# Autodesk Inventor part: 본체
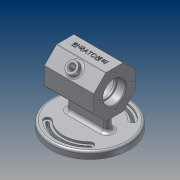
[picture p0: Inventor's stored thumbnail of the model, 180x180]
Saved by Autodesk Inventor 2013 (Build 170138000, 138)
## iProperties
Created: 2017-06
Part Number: 본체
Material: 알루미늄 6061
Document SubType Name: Modeling
Designer: Windows7
Density: 2.71 g/cm^3
Mass: 559.992 g
Surface Area: 567.6 cm^2
Volume: 206.639 cm^3
Author: Windows7
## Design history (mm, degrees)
sketch "스케치1" dims "d0" = 60
  geometry: L1 (12.426, 30)-(30, 12.426); L2 (30, 12.426)-(30, -12.426); L3 (30, -12.426)-(12.426, -30); L4 (12.426, -30)-(-12.426, -30); L5 (-12.426, -30)-(-30, -12.426); L6 (-30, -12.426)-(-30, 12.426); L7 (-30, 12.426)-(-12.426, 30); L8 (-12.426, 30)-(12.426, 30); 4 further points
  constraints: 16 end point, 2 coincident, 2 vertical alignment, 1 midpoint, 19 other
extrude "돌출1" new body sketch "스케치1" stored distance "d1" = 70; taper "d2" = 0 deg
sketch "스케치2"
  geometry: C1 r 25 at (0, 0); 1 further point
  constraints: 1 centre point, 1 coincident
  dimensions: "d3" = 50 diameter of C1
extrude "돌출2" cut sketch "스케치2" stored distance "d4" = 40; taper "d5" = 0 deg
sketch "스케치3"
  geometry: 1 further point
hole "구멍1" sketch "스케치3" at (0, 0) diameter "d6" = 28; stored, may be unused: countersink angle "d10" = 90 deg, drill point angle "d12" = 0 deg; dims "d7" = 6, "d8" = 32, "d9" = 12, "d11" = 15
chamfer "모따기1" distance "d13" = 1; stored, may be unused: second distance "d14" = 2, angle "d15" = 45 deg
node "작업 평면1"
sketch "스케치4"
  geometry: C1 r 55 at (0, 0); 1 further point
  constraints: 1 centre point, 1 coincident
  dimensions: "d17" = 110 diameter of C1
extrude "돌출3" join sketch "스케치4" distance "d18" = 10; taper "d19" = 0 deg
sketch "스케치5" dims "d20" = 86
  geometry: L1 (0, 55)-(0, -55); L2 (0, 0)-(-38.891, 38.891); A1 r 55 centre (0, 0) between (0, 55) and (0, -55) reference; A2 r 48 centre (0, 0) between (33.941, 33.941) and (-33.941, 33.941); A3 r 38 centre (0, 0) between (26.87, 26.87) and (-26.87, 26.87); A4 r 5 centre (-30.406, 30.406) between (-33.941, 33.941) and (-26.87, 26.87); A5 r 5 centre (30.406, 30.406) between (26.87, 26.87) and (33.941, 33.941)
  constraints: 11 point on circle, 4 centre point, 4 end point, 2 coincident, 1 midpoint, 1 point on line, 1 symmetric about line, 1 tangent, 1 vertical, 4 other
  dimensions: "d21" = 45 deg angle of L1 L2; "d23" = 96 diameter of A2; "d24" = 76 diameter of A3
extrude "돌출4" cut sketch "스케치5" distance "d25" = 3; taper "d26" = 0 deg
sketch "스케치6"
  geometry: A1 r 5 centre (-30.406, 30.406) between (-33.941, 33.941) and (-26.87, 26.87) reference; A2 r 38 centre (0, 0) between (26.87, 26.87) and (-26.87, 26.87) reference; A3 r 5 centre (30.406, 30.406) between (26.87, 26.87) and (33.941, 33.941) reference; A4 r 48 centre (0, 0) between (33.941, 33.941) and (-33.941, 33.941) reference; A5 r 2 centre (-30.406, 30.406) between (-31.82, 31.82) and (-28.991, 28.991); A6 r 41 centre (0, 0) between (28.991, 28.991) and (-28.991, 28.991); A7 r 2 centre (30.406, 30.406) between (28.991, 28.991) and (31.82, 31.82); A8 r 45 centre (0, 0) between (31.82, 31.82) and (-31.82, 31.82)
  constraints: 8 point on circle, 4 centre point, 3 other
  dimensions: "d27" = 3 radial gap between concentric circles of A8 A4
extrude "돌출5" cut sketch "스케치6" stored distance "d28" = 3; taper "d29" = 0 deg
sketch "스케치8"
  geometry: L1 (-24, -5)-(24, -5); L2 (24, -5)-(24, 5); L3 (24, 5)-(-24, 5); L4 (-24, 5)-(-24, -5); L5 (-24, -5)-(24, 5); L6 (24, -5)-(-24, 5); A1 r 38 centre (0, 0) between (-26.87, -26.87) and (26.87, -26.87) reference; 4 further points
  constraints: 12 end point, 5 midpoint, 2 parallel, 2 vertical alignment, 1 coincident, 1 horizontal, 1 perpendicular, 4 other
  dimensions: "d30" = 48 distance of L2.end L3.end; "d32" = 10 distance of L1.end L2.end
extrude "돌출6" join sketch "스케치8" stored distance "d33" = 3; taper "d34" = 0 deg
sketch "스케치9"
  geometry: L1 (70, 42.426)-(0, 42.426) reference; L2 (0, 24.853)-(0, 42.426) reference; 2 further points
  constraints: 1 other
  dimensions: "d36" = 30 distance from line of L1 point (35, 12.426); "d73" = 35 distance from line of point (35, 12.426) L2
feature "엠보싱1" sketch "스케치9" dims "d37" = 0.5, "d38" = 0
sketch "스케치10"
  geometry: L1 (30, 12.426)-(12.426, 30) reference; L2 (12.426, 30)-(-12.426, 30) reference; L3 (-12.426, 30)-(-30, 12.426) reference; L4 (-30, 12.426)-(-30, -12.426) reference; L5 (-30, -12.426)-(-12.426, -30) reference; L6 (-12.426, -30)-(12.426, -30) reference; L7 (12.426, -30)-(30, -12.426) reference; L8 (30, -12.426)-(30, 12.426) reference; L9 (30, 0)-(-30, 0); L10 (0, 0)-(26.163, 26.163); C1 r 17 at (0, 0) reference; 1 further point
  constraints: 5 end point, 3 midpoint
  dimensions: "d42" = 45 deg angle of L10 L9; "d43" = 7 distance from line of L10.end L1
  node "투영된 루프1"
node "작업 평면2"
sketch "스케치11"
  geometry: C1 r 8 at (0, 0); 1 further point
  constraints: 1 centre point, 1 coincident
  dimensions: "d44" = 16 diameter of C1
extrude "돌출7" join sketch "스케치11" stored distance "d45" = 3; taper "d46" = 0 deg
sketch "스케치12"
  geometry: C1 r 8 at (0, 0) reference
hole "구멍2" sketch "스케치12" at (0, 0) diameter "d47" = 8; stored, may be unused: countersink angle "d51" = 90 deg, drill point angle "d53" = 0 deg; dims "d48" = 6, "d49" = 32, "d50" = 12, "d52" = 15
fillet "모깎기1" dims "d54" = 3
chamfer "모따기2" distance "d55" = 1; stored, may be unused: second distance "d56" = 2, angle "d57" = 45 deg
fillet "모깎기2" dims "d58" = 1
fillet "모깎기3" dims "d59" = 0.3
fillet "모깎기4" dims "d60" = 3
sketch "스케치13"
  geometry: C1 r 17 at (0, 0) reference; 1 further point
  constraints: 1 vertical alignment
  dimensions: "d62" = 23 distance of C1.centre point (0, 23)
hole "구멍3" sketch "스케치13" at (0, 23) diameter "d63" = 3.242; stored, may be unused: countersink angle "d67" = 90 deg, drill point angle "d69" = 118 deg; dims "d64" = 8, "d65" = 32, "d66" = 12, "d68" = 10
fillet "모깎기6" dims "d74" = 5
fillet "모깎기7" dims "d75" = 3
node "솔리드1"
mirror "대칭1"
mirror "대칭2"
pattern_circular "원형 패턴1" dims angle "d71" = 360 deg
mirror "대칭3"
other parameters: "d16" = -62
